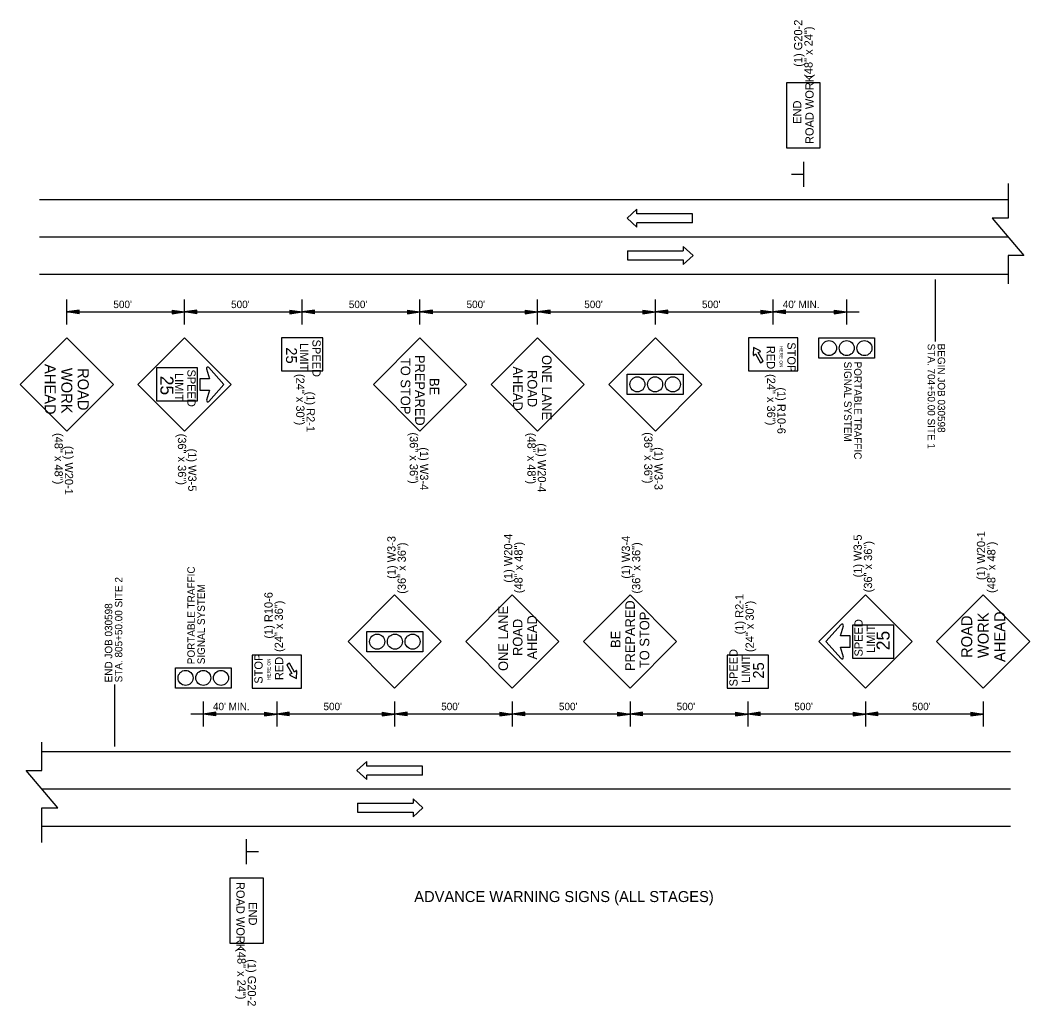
# Model space of a CAD drawing. Extents: x 1368648 to 1927880, y -1037443 to 380209.
# Drawn here: x 1370251 to 1370987, y 376133 to 376851 of the extents above; entities that cross this region are included whole.
import ezdxf

# ---------------------------------------------------------------- set-up
doc = ezdxf.new("R2010")
doc.units = 0
for name, color, linetype in [('Default', 7, 'Continuous'), ('Dimensions', 7, 'Continuous'), ('R_Draft', 7, 'Continuous'), ('R_Signs', 7, 'Continuous'), ('R_Signs_Annot', 7, 'Continuous')]:
    doc.layers.add(name, color=color, linetype=linetype)

# ---------------------------------------------------------------- blocks, each defined once
blk = doc.blocks.new('ARROW')
at = {"layer": 'R_Draft'}
for p, q in [((-2, 0.3), (0, 0)), ((-2, 0.3), (-2, -0.3)), ((-2, 0.25), (-0.334, 0)), ((-2, 0.199), (-0.678, 0)), ((-2, 0.149), (-1.011, 0)), ((-2, 0.097), (-1.35, 0)), ((-2, 0.047), (-1.684, 0)), ((-2, -0.3), (0, 0)), ((-2, -0.098), (-1.35, 0)), ((-2, -0.199), (-0.678, 0)), ((-2, -0.25), (-0.334, 0)), ((-2, -0.149), (-1.011, 0)), ((-2, -0.047), (-1.684, 0))]:
    blk.add_line(p, q, dxfattribs=at)

msp = doc.modelspace()

# ---------------------------------------------------------------- linework, layer by layer
at = {"layer": 'Default'}
for p, q in [((1370822.06, 376729.41), (1370822.06, 376747.46)), ((1370822.06, 376738.44), (1370813.04, 376738.44)), ((1370265.41, 376720.01), (1370970.79, 376720.01)), ((1370265.41, 376692.94), (1370970.79, 376692.94)), ((1370265.41, 376665.86), (1370970.79, 376665.86)), ((1370917.76, 376661.77), (1370917.76, 376616.64)), ((1370285.24, 376629.2), (1370285.24, 376647.25)), ((1370370.98, 376629.2), (1370370.98, 376647.25)), ((1370370.98, 376629.2), (1370370.98, 376647.25)), ((1370456.72, 376629.2), (1370456.72, 376647.25)), ((1370456.72, 376629.2), (1370456.72, 376647.25)), ((1370542.46, 376629.2), (1370542.46, 376647.25)), ((1370542.46, 376629.2), (1370542.46, 376647.25)), ((1370628.19, 376629.2), (1370628.19, 376647.25)), ((1370713.93, 376629.2), (1370713.93, 376647.25)), ((1370799.67, 376629.2), (1370799.67, 376647.25)), ((1370853.28, 376629.2), (1370853.28, 376647.25)), ((1370285.24, 376638.22), (1370370.98, 376638.22)), ((1370285.24, 376638.22), (1370294.27, 376638.22)), ((1370370.98, 376638.22), (1370456.72, 376638.22)), ((1370370.98, 376638.22), (1370380.01, 376638.22)), ((1370370.98, 376638.22), (1370380.01, 376638.22)), ((1370456.72, 376638.22), (1370465.74, 376638.22)), ((1370456.72, 376638.22), (1370542.46, 376638.22)), ((1370456.72, 376638.22), (1370465.74, 376638.22)), ((1370542.46, 376638.22), (1370551.48, 376638.22)), ((1370542.46, 376638.22), (1370628.19, 376638.22)), ((1370542.46, 376638.22), (1370551.48, 376638.22)), ((1370628.19, 376638.22), (1370713.93, 376638.22)), ((1370628.19, 376638.22), (1370637.22, 376638.22)), ((1370713.93, 376638.22), (1370799.67, 376638.22)), ((1370713.93, 376638.22), (1370722.96, 376638.22)), ((1370799.67, 376638.22), (1370808.69, 376638.22)), ((1370799.67, 376638.22), (1370853.28, 376638.22)), ((1370853.28, 376638.22), (1370862.31, 376638.22)), ((1370320.18, 376321.85), (1370320.18, 376366.98)), ((1370384.65, 376354.42), (1370384.65, 376336.37)), ((1370438.27, 376354.42), (1370438.27, 376336.37)), ((1370524, 376354.42), (1370524, 376336.37)), ((1370609.74, 376354.42), (1370609.74, 376336.37)), ((1370695.48, 376354.42), (1370695.48, 376336.37)), ((1370695.48, 376354.42), (1370695.48, 376336.37)), ((1370781.22, 376354.42), (1370781.22, 376336.37)), ((1370781.22, 376354.42), (1370781.22, 376336.37)), ((1370866.95, 376354.42), (1370866.95, 376336.37)), ((1370866.95, 376354.42), (1370866.95, 376336.37)), ((1370952.69, 376354.42), (1370952.69, 376336.37)), ((1370384.65, 376345.4), (1370375.63, 376345.4)), ((1370438.27, 376345.4), (1370384.65, 376345.4)), ((1370438.27, 376345.4), (1370429.24, 376345.4)), ((1370524, 376345.4), (1370438.27, 376345.4)), ((1370524, 376345.4), (1370514.98, 376345.4)), ((1370609.74, 376345.4), (1370524, 376345.4)), ((1370609.74, 376345.4), (1370600.72, 376345.4)), ((1370695.48, 376345.4), (1370609.74, 376345.4)), ((1370695.48, 376345.4), (1370686.45, 376345.4)), ((1370695.48, 376345.4), (1370686.45, 376345.4)), ((1370781.22, 376345.4), (1370695.48, 376345.4)), ((1370781.22, 376345.4), (1370772.19, 376345.4)), ((1370781.22, 376345.4), (1370772.19, 376345.4)), ((1370866.95, 376345.4), (1370781.22, 376345.4)), ((1370866.95, 376345.4), (1370857.93, 376345.4)), ((1370866.95, 376345.4), (1370857.93, 376345.4)), ((1370952.69, 376345.4), (1370866.95, 376345.4)), ((1370952.69, 376345.4), (1370943.67, 376345.4)), ((1370972.52, 376317.76), (1370267.15, 376317.76)), ((1370972.52, 376290.68), (1370267.15, 376290.68)), ((1370972.52, 376263.61), (1370267.15, 376263.61)), ((1370415.87, 376254.2), (1370415.87, 376236.15)), ((1370415.87, 376245.18), (1370424.9, 376245.18))]:
    msp.add_line(p, q, dxfattribs=at)
for points in [[(1370970.79, 376731.88), (1370970.79, 376706.48), (1370959.2, 376706.48), (1370982.37, 376679.4), (1370970.79, 376679.4), (1370970.79, 376658.74)], [(1370267.15, 376251.74), (1370267.15, 376277.14), (1370278.74, 376277.14), (1370255.56, 376304.22), (1370267.15, 376304.22), (1370267.15, 376324.88)]]:
    msp.add_lwpolyline(points, dxfattribs=at)
at = {"layer": 'Dimensions'}
for p, q in [((1370740.97, 376703.23), (1370700.39, 376703.23)), ((1370693.64, 376682.65), (1370734.22, 376682.65)), ((1370544.29, 376300.97), (1370503.71, 376300.97)), ((1370496.97, 376280.39), (1370537.55, 376280.39))]:
    msp.add_line(p, q, dxfattribs=at)
for points in [[(1370740.97, 376703.23), (1370740.97, 376709.72), (1370700.39, 376709.72), (1370700.39, 376712.97), (1370693.26, 376706.48), (1370700.39, 376699.98), (1370700.39, 376703.23)], [(1370693.64, 376682.65), (1370693.64, 376676.15), (1370734.22, 376676.15), (1370734.22, 376672.9), (1370741.35, 376679.4), (1370734.22, 376685.9), (1370734.22, 376682.65)], [(1370544.29, 376300.97), (1370544.29, 376307.47), (1370503.71, 376307.47), (1370503.71, 376310.72), (1370496.59, 376304.22), (1370503.71, 376297.72), (1370503.71, 376300.97)], [(1370496.97, 376280.39), (1370496.97, 376273.9), (1370537.55, 376273.9), (1370537.55, 376270.65), (1370544.67, 376277.14), (1370537.55, 376283.64), (1370537.55, 376280.39)]]:
    msp.add_lwpolyline(points, dxfattribs=at)
at = {"layer": 'R_Signs'}
for p, q in [((1370370.98, 376619.32), (1370337.04, 376585.38)), ((1370404.92, 376585.38), (1370370.98, 376619.32)), ((1370542.46, 376619.32), (1370508.52, 376585.38)), ((1370576.4, 376585.38), (1370542.46, 376619.32)), ((1370628.19, 376619.32), (1370594.25, 376585.38)), ((1370662.14, 376585.38), (1370628.19, 376619.32)), ((1370713.93, 376619.32), (1370679.99, 376585.38)), ((1370747.87, 376585.38), (1370713.93, 376619.32)), ((1370832.96, 376604.51), (1370832.96, 376619.32)), ((1370832.96, 376619.32), (1370873.6, 376619.32)), ((1370873.6, 376619.32), (1370873.6, 376604.51)), ((1370785.46, 376612.32), (1370785.21, 376607)), ((1370785.21, 376607), (1370785.21, 376607)), ((1370790.19, 376609.87), (1370785.46, 376612.32)), ((1370785.92, 376606.7), (1370786.86, 376607.7)), ((1370785.92, 376606.7), (1370785.92, 376606.7)), ((1370786.86, 376607.7), (1370790.6, 376601.23)), ((1370788.75, 376608.8), (1370790.09, 376609.11)), ((1370792.49, 376602.33), (1370788.75, 376608.8)), ((1370790.09, 376609.11), (1370790.09, 376609.11)), ((1370790.19, 376609.87), (1370790.19, 376609.87)), ((1370790.6, 376601.23), (1370792.49, 376602.33)), ((1370873.6, 376604.51), (1370832.96, 376604.51)), ((1370387.08, 376596.91), (1370389.14, 376589.41)), ((1370399.74, 376585.38), (1370388.72, 376597.8)), ((1370693.42, 376578.09), (1370693.42, 376592.89)), ((1370693.42, 376592.89), (1370734.07, 376592.89)), ((1370734.07, 376592.89), (1370734.07, 376578.09)), ((1370337.04, 376585.38), (1370370.98, 376551.44)), ((1370370.98, 376551.44), (1370404.92, 376585.38)), ((1370382.07, 376589.41), (1370382.07, 376581.29)), ((1370389.14, 376589.41), (1370382.07, 376589.41)), ((1370388.74, 376572.99), (1370399.74, 376585.38)), ((1370508.52, 376585.38), (1370542.46, 376551.46)), ((1370542.46, 376551.46), (1370576.4, 376585.38)), ((1370594.25, 376585.38), (1370628.19, 376551.46)), ((1370628.19, 376551.46), (1370662.14, 376585.38)), ((1370679.99, 376585.38), (1370713.93, 376551.44)), ((1370713.93, 376551.44), (1370747.87, 376585.38)), ((1370382.07, 376581.29), (1370389.14, 376581.29)), ((1370389.14, 376581.29), (1370387.1, 376573.88)), ((1370734.07, 376578.09), (1370693.42, 376578.09)), ((1370524, 376432.18), (1370490.06, 376398.24)), ((1370557.94, 376398.24), (1370524, 376432.18)), ((1370609.74, 376432.16), (1370575.8, 376398.24)), ((1370643.68, 376398.24), (1370609.74, 376432.16)), ((1370695.48, 376432.16), (1370661.54, 376398.24)), ((1370729.42, 376398.24), (1370695.48, 376432.16)), ((1370866.95, 376432.18), (1370833.01, 376398.24)), ((1370900.89, 376398.24), (1370866.95, 376432.18)), ((1370849.19, 376410.63), (1370838.19, 376398.24)), ((1370848.8, 376402.33), (1370850.84, 376409.74)), ((1370503.87, 376390.73), (1370503.87, 376405.53)), ((1370503.87, 376405.53), (1370544.51, 376405.53)), ((1370544.51, 376405.53), (1370544.51, 376390.73)), ((1370855.87, 376402.33), (1370848.8, 376402.33)), ((1370855.87, 376394.21), (1370855.87, 376402.33)), ((1370490.06, 376398.24), (1370524, 376364.3)), ((1370524, 376364.3), (1370557.94, 376398.24)), ((1370575.8, 376398.24), (1370609.74, 376364.3)), ((1370609.74, 376364.3), (1370643.68, 376398.24)), ((1370661.54, 376398.24), (1370695.48, 376364.3)), ((1370695.48, 376364.3), (1370729.42, 376398.24)), ((1370833.01, 376398.24), (1370866.95, 376364.3)), ((1370838.19, 376398.24), (1370849.21, 376385.82)), ((1370850.86, 376386.71), (1370848.8, 376394.21)), ((1370848.8, 376394.21), (1370855.87, 376394.21)), ((1370866.95, 376364.3), (1370900.89, 376398.24)), ((1370544.51, 376390.73), (1370503.87, 376390.73)), ((1370364.33, 376364.3), (1370364.33, 376379.11)), ((1370364.33, 376379.11), (1370404.97, 376379.11)), ((1370404.97, 376379.11), (1370404.97, 376364.3)), ((1370447.34, 376382.39), (1370445.45, 376381.29)), ((1370445.45, 376381.29), (1370449.18, 376374.82)), ((1370451.07, 376375.91), (1370447.34, 376382.39)), ((1370447.75, 376373.75), (1370447.75, 376373.75)), ((1370447.75, 376373.75), (1370452.48, 376371.29)), ((1370449.18, 376374.82), (1370447.84, 376374.51)), ((1370447.84, 376374.51), (1370447.84, 376374.51)), ((1370452.01, 376376.92), (1370451.07, 376375.91)), ((1370452.01, 376376.92), (1370452.01, 376376.92)), ((1370452.48, 376371.29), (1370452.72, 376376.62)), ((1370452.72, 376376.62), (1370452.72, 376376.62)), ((1370404.97, 376364.3), (1370364.33, 376364.3))]:
    msp.add_line(p, q, dxfattribs=at)
for points in [[(1370809.67, 376757.4), (1370809.67, 376805.4), (1370833.67, 376805.4), (1370833.67, 376757.4)], [(1370319.19, 376585.38), (1370285.24, 376619.32), (1370251.3, 376585.38), (1370285.24, 376551.44)], [(1370441.72, 376619.32), (1370441.72, 376595.32), (1370471.72, 376595.32), (1370471.72, 376619.32)], [(1370781.67, 376619.32), (1370781.67, 376595.32), (1370817.67, 376595.32), (1370817.67, 376619.32)], [(1370350.46, 376597.54), (1370350.46, 376573.51), (1370380.49, 376573.51), (1370380.49, 376597.54)], [(1370918.75, 376398.24), (1370952.69, 376364.3), (1370986.63, 376398.24), (1370952.69, 376432.18)], [(1370887.48, 376386.08), (1370887.48, 376410.11), (1370857.45, 376410.11), (1370857.45, 376386.08)], [(1370456.27, 376364.3), (1370456.27, 376388.3), (1370420.27, 376388.3), (1370420.27, 376364.3)], [(1370796.22, 376364.3), (1370796.22, 376388.3), (1370766.22, 376388.3), (1370766.22, 376364.3)], [(1370428.26, 376226.22), (1370428.26, 376178.22), (1370404.26, 376178.22), (1370404.26, 376226.22)]]:
    msp.add_lwpolyline(points, close=True, dxfattribs=at)
for centre in [(1370840.37, 376611.92), (1370853.28, 376611.92), (1370853.28, 376611.92), (1370866.18, 376611.92), (1370700.83, 376585.49), (1370713.74, 376585.49), (1370713.74, 376585.49), (1370726.64, 376585.49), (1370511.29, 376398.13), (1370524.2, 376398.13), (1370524.2, 376398.13), (1370537.1, 376398.13), (1370371.76, 376371.7), (1370384.66, 376371.7), (1370384.66, 376371.7), (1370397.56, 376371.7)]:
    msp.add_circle(centre, 5.48, dxfattribs=at)
for centre, radius, start, end in [((1370785.62, 376606.98), 0.41, 177.40326, 316.94368), ((1370790, 376609.51), 0.41, 283.0563, 62.59672), ((1370388, 376597.16), 0.961, 41.58619, 195.37776), ((1370388.03, 376573.62), 0.961, 164.62224, 318.41381), ((1370849.91, 376410), 0.961, 344.62224, 138.41381), ((1370849.93, 376386.46), 0.961, 221.58619, 15.37776), ((1370447.94, 376374.11), 0.41, 103.0563, 242.59672), ((1370452.31, 376376.64), 0.41, 357.40326, 136.94368)]:
    msp.add_arc(centre, radius, start, end, dxfattribs=at)

# ---------------------------------------------------------------- block references
at = {"layer": 'Default', "xscale": 4.512500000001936, "yscale": 4.512499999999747, "rotation": 180}
for p in [(1370285.24, 376638.22), (1370370.98, 376638.22), (1370456.72, 376638.22), (1370542.46, 376638.22), (1370628.19, 376638.22), (1370628.19, 376638.22), (1370713.93, 376638.22), (1370713.93, 376638.22), (1370799.67, 376638.22), (1370384.65, 376345.4), (1370438.27, 376345.4), (1370438.27, 376345.4), (1370524, 376345.4), (1370524, 376345.4), (1370609.74, 376345.4), (1370695.48, 376345.4), (1370781.22, 376345.4), (1370866.95, 376345.4)]:
    msp.add_blockref('ARROW', p, dxfattribs=at)
at = {"layer": 'Default', "xscale": 4.512500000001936, "yscale": 4.512499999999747}
for p in [(1370370.98, 376638.22), (1370456.72, 376638.22), (1370542.46, 376638.22), (1370628.19, 376638.22), (1370713.93, 376638.22), (1370713.93, 376638.22), (1370799.67, 376638.22), (1370799.67, 376638.22), (1370853.28, 376638.22), (1370438.27, 376345.4), (1370524, 376345.4), (1370524, 376345.4), (1370609.74, 376345.4), (1370609.74, 376345.4), (1370695.48, 376345.4), (1370781.22, 376345.4), (1370866.95, 376345.4), (1370952.69, 376345.4)]:
    msp.add_blockref('ARROW', p, dxfattribs=at)

# ---------------------------------------------------------------- texts
at = {"layer": 'Default'}
for s, height, p in [("500'", 5.415, (1370319.18, 376641.03)), ("500'", 5.415, (1370404.92, 376641.03)), ("500'", 5.415, (1370490.65, 376641.03)), ("500'", 5.415, (1370576.39, 376641.03)), ("500'", 5.415, (1370662.13, 376641.03)), ("500'", 5.415, (1370747.87, 376641.03)), ("40' MIN.", 5.415, (1370806.71, 376641.03)), ('ADVANCE WARNING SIGNS (ALL STAGES)', 8, (1370538.29, 376208.48))]:
    msp.add_text(s, height=height, dxfattribs=at).set_placement(p)
for s, rotation, p in [('STA. 704+50.00 SITE 1', 270, (1370912.24, 376615.14)), ('BEGIN JOB 030598', 270, (1370919.57, 376615.14)), ('SIGNAL SYSTEM', 270, (1370851.38, 376602.05)), ('PORTABLE TRAFFIC ', 270, (1370858.71, 376602.05)), ('PORTABLE TRAFFIC ', 90, (1370378.47, 376381.66)), ('STA. 805+50.00 SITE 2', 90, (1370325.7, 376368.47)), ('SIGNAL SYSTEM', 90, (1370385.8, 376381.66)), ('END JOB 030598', 90, (1370318.36, 376368.47)), ("40' MIN.", 360, (1370391.69, 376348.2)), ("500'", 360, (1370472.2, 376348.2)), ("500'", 360, (1370557.94, 376348.2)), ("500'", 360, (1370643.67, 376348.2)), ("500'", 360, (1370729.41, 376348.2)), ("500'", 360, (1370815.15, 376348.2)), ("500'", 360, (1370900.89, 376348.2))]:
    msp.add_text(s, height=5.415, rotation=rotation, dxfattribs=at).set_placement(p)
at = {"layer": 'R_Signs'}
for s, height, rotation, p in [('ROAD WORK', 6, 90, (1370829.17, 376760.53)), ('END', 6, 90, (1370820.17, 376775.24)), ('LIMIT', 6, 270, (1370455.13, 376615.54)), ('SPEED', 6, 270, (1370464.13, 376618.1)), ('STOP', 6, 270, (1370810.08, 376616.13)), ('25', 8, 270, (1370444.9, 376612.45)), ('ONE LANE', 7, 270, (1370631.31, 376606.83)), ('RED', 6, 270, (1370795.08, 376613.5)), ('HERE ON', 2.5, 270, (1370804.33, 376613.47)), ('AHEAD', 8, 270, (1370269.24, 376600.33)), ('TO STOP', 7, 270, (1370528.46, 376604.73)), ('PREPARED', 7, 270, (1370538.96, 376606.91)), ('WORK', 8, 270, (1370281.24, 376597.5)), ('ROAD', 8, 270, (1370293.24, 376597.36)), ('LIMIT', 6, 270, (1370364.05, 376593.75)), ('SPEED', 6, 270, (1370373.05, 376596.31)), ('AHEAD', 7, 270, (1370610.31, 376598.5)), ('ROAD', 7, 270, (1370620.81, 376595.94)), ('25', 9.5, 270, (1370353.43, 376591.75)), ('BE', 7, 270, (1370549.46, 376590.07)), ('ONE LANE', 7, 90, (1370606.62, 376376.79)), ('PREPARED', 7, 90, (1370698.98, 376376.71)), ('AHEAD', 7, 90, (1370627.62, 376385.12)), ('TO STOP', 7, 90, (1370709.48, 376378.88)), ('ROAD', 8, 90, (1370944.69, 376386.26)), ('WORK', 8, 90, (1370956.69, 376386.12)), ('AHEAD', 8, 90, (1370968.69, 376383.28)), ('ROAD', 7, 90, (1370617.12, 376387.68)), ('SPEED', 6, 90, (1370864.89, 376387.31)), ('LIMIT', 6, 90, (1370873.89, 376389.87)), ('BE', 7, 90, (1370688.48, 376393.55)), ('25', 9.5, 90, (1370884.51, 376391.87)), ('STOP', 6, 90, (1370427.86, 376367.49)), ('RED', 6, 90, (1370442.86, 376370.12)), ('SPEED', 6, 90, (1370773.81, 376365.52)), ('LIMIT', 6, 90, (1370782.81, 376368.08)), ('HERE ON', 2.5, 90, (1370433.61, 376370.15)), ('25', 8, 90, (1370793.04, 376371.17)), ('ROAD WORK', 6, 270, (1370408.76, 376223.09)), ('END', 6, 270, (1370417.76, 376208.38))]:
    msp.add_text(s, height=height, rotation=rotation, dxfattribs=at).set_placement(p)
at = {"layer": 'R_Signs_Annot'}
for s, rotation, p in [('(1) G20-2', 90, (1370820.91, 376816.77)), ('(48" x 24")', 90, (1370828.43, 376808.74)), ('(24" x 30")', 270, (1370452.33, 376593.09)), ('(24" x 36")', 270, (1370795.28, 376592.99)), ('(1) R2-1', 270, (1370459.84, 376580.19)), ('(1) R10-6', 270, (1370802.79, 376583.28)), ('(48" x 48")', 270, (1370276.34, 376550.06)), ('(36" x 36")', 270, (1370366.16, 376549.58)), ('(36" x 36")', 270, (1370535.02, 376550.5)), ('(48" x 48")', 270, (1370620.75, 376550.22)), ('(36" x 36")', 270, (1370705.77, 376550.64)), ('(1) W20-1', 270, (1370283.85, 376540.7)), ('(1) W20-4', 270, (1370628.27, 376542.56)), ('(1) W3-5', 270, (1370373.67, 376538.71)), ('(1) W3-4', 270, (1370542.53, 376539.63)), ('(1) W3-3', 270, (1370713.28, 376539.77)), ('(1) W3-3', 90, (1370524.66, 376443.85)), ('(1) W20-4', 90, (1370609.67, 376441.06)), ('(1) W3-4', 90, (1370695.41, 376443.98)), ('(1) W3-5', 90, (1370864.26, 376444.91)), ('(1) W20-1', 90, (1370954.08, 376442.92)), ('(36" x 36")', 90, (1370532.17, 376432.98)), ('(48" x 48")', 90, (1370617.18, 376433.4)), ('(36" x 36")', 90, (1370702.92, 376433.12)), ('(36" x 36")', 90, (1370871.77, 376434.04)), ('(48" x 48")', 90, (1370961.59, 376433.56)), ('(1) R10-6', 90, (1370435.14, 376400.33)), ('(1) R2-1', 90, (1370778.09, 376403.43)), ('(24" x 36")', 90, (1370442.65, 376390.63)), ('(24" x 30")', 90, (1370785.6, 376390.53)), ('(48" x 24")', 270, (1370409.51, 376174.88)), ('(1) G20-2', 270, (1370417.02, 376166.85))]:
    msp.add_text(s, height=6, rotation=rotation, dxfattribs=at).set_placement(p)

doc.saveas('drawing.dxf')
